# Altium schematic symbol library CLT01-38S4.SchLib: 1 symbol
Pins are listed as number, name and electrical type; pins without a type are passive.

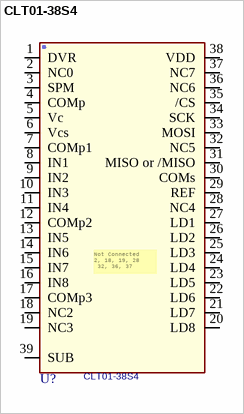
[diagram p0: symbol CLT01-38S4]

## CLT01-38S4
designator U?
footprint ST_HTSSOP-38
pins: 1 DVR, 2 NC0, 3 SPM, 4 COMp, 5 Vc, 6 Vcs, 7 COMp1, 8 IN1, 9 IN2, 10 IN3, 11 IN4, 12 COMp2, 13 IN5, 14 IN6, 15 IN7, 16 IN8, 17 COMp3, 18 NC2, 19 NC3, 20 LD8, 21 LD7, 22 LD6, 23 LD5, 24 LD4, 25 LD3, 26 LD2, 27 LD1, 28 NC4, 29 REF, 30 COMs, 31 MISO or /MISO, 32 NC5, 33 MOSI, 34 SCK, 35 /CS, 36 NC6, 37 NC7, 38 VDD, 39 SUB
